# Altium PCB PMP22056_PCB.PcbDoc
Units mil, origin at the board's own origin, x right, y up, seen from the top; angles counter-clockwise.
Board outline 984.25 x 984.25 mil, 2 copper layers (Top Layer, Bottom Layer), stack 62 mil thick; 21 components, 12 nets, 49 pads, 5 vias.
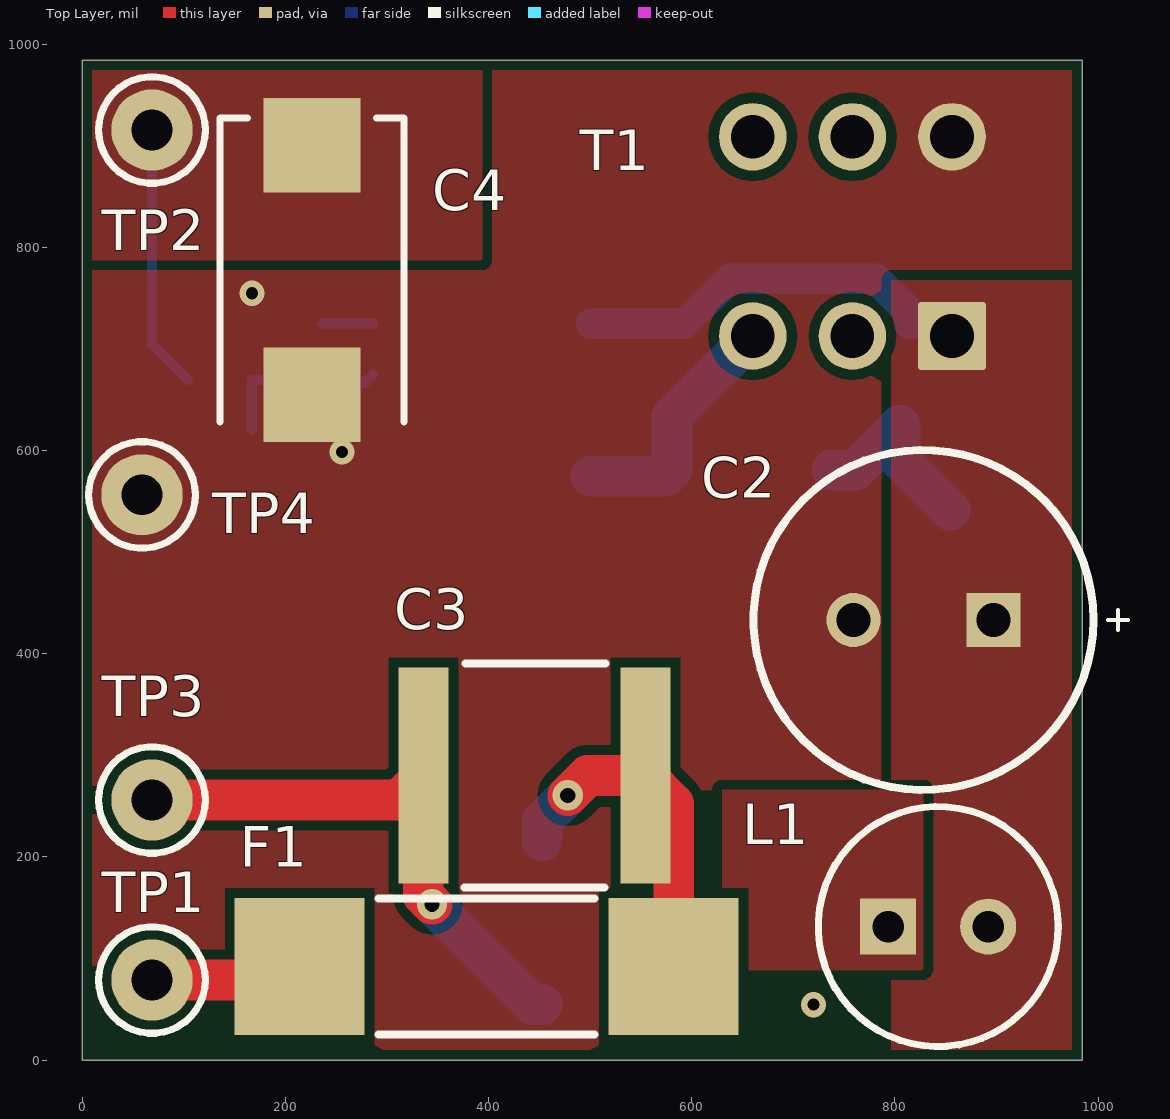
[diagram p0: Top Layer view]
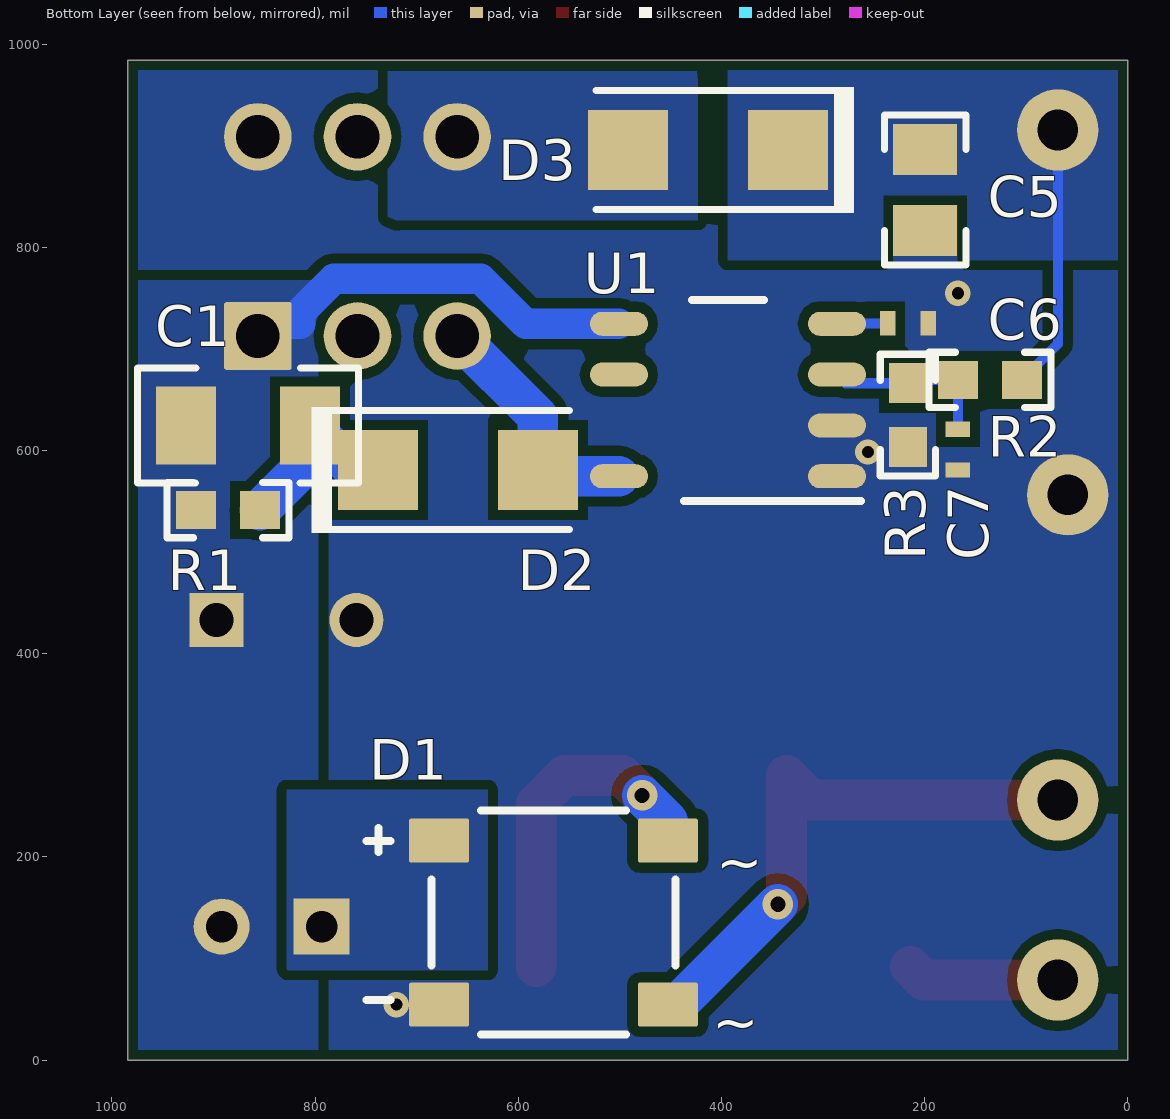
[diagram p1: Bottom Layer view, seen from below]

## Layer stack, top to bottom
Top Solder: solder mask 0.4, Solder Resist, Dk 3.5
Top Layer: signal copper 1.4
Dielectric1: core 59.2, FR-4, Dk 4.8
Bottom Layer: signal copper 1.4
Bottom Solder: solder mask 0.4, Solder Resist, Dk 3.5

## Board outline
0,0 0,984.25 984.25,984.25 984.25,0

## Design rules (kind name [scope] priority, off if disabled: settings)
AcuteAngle [All] p1: minimum=4.50000000000000E+0001 checktracksonly=FALSE
AssemblyTestPointUsage [All] p1: valid=2
BoardOutlineClearance BoardOutlineClearance_MountingHoles [OnCopper and InComponentClass('Mounting Holes')] p1: gap=10 ignorepadtopadclearanceinfootprint=FALSE
BoardOutlineClearance BoardOutlineClearance_Poly [OnCopper and IsPoly] p2: gap=10 ignorepadtopadclearanceinfootprint=FALSE
BoardOutlineClearance [OnCopper and Not InComponentClass('Logo') and not InComponentClass('FiducialMark') and not InRegion(1000,500,4000,800) and not InPoly] p3: gap=10 ignorepadtopadclearanceinfootprint=FALSE
Clearance Clearance_Keepouts [((IsTrack Or IsArc) And Not InPoly) And IsFree and IsKeepOut vs ((IsTrack Or IsArc) And Not InPoly) And IsFree and IsKeepOut] p1: gap=0 ignorepadtopadclearanceinfootprint=FALSE
Clearance Clearance_Poly [InPolygon] p2: gap=10 ignorepadtopadclearanceinfootprint=TRUE
Clearance Clearance_FiducialMark [IsKeepOut and InComponentClass('FiducialMark') vs IsPad and InComponentClass('FiducialMark')] p3: gap=0 ignorepadtopadclearanceinfootprint=FALSE
Clearance [All] p4: gap=7.87 ignorepadtopadclearanceinfootprint=TRUE
ComponentClearance ComponentClearance_MountingHoles_FiducialMarks [InComponentClass('Mounting Holes') vs InComponentClass('FiducialMark')] p1: gap=10 collisioncheckmode=3 verticalgap=10 showdistances=FALSE
ComponentClearance ComponentClearance_Shunt [InComponentClass('Header') vs InComponentClass('Shunt')] p2: gap=0 collisioncheckmode=3 verticalgap=0 showdistances=FALSE
ComponentClearance ComponentClearance_Logo [InComponentClass('Logo')] p3: gap=10 collisioncheckmode=3 verticalgap=10 showdistances=FALSE
ComponentClearance ComponentClearance_ScrewToNut [(HasFootprint('NY PMS 440 0025 PH')) vs (HasFootprint('Keystone_1902C'))] p4: gap=5 collisioncheckmode=3 verticalgap=10 showdistances=FALSE
ComponentClearance ComponentClearance_MountingHoles [InComponentClass('Mounting Holes')] p5: gap=250 collisioncheckmode=3 verticalgap=100000 showdistances=FALSE
ComponentClearance ComponentClearance_SmallPassives [HasFootprint('0201*') or HasFootprint('0402*') or HasFootprint('0508') or HasFootprint('0603*') or HasFootprint('0612') or HasFootprint('0805*') or HasFootprint('0815*') or HasFootprint('0830*') or HasFootprint('1206*') or HasFootprint('1210*') or HasFootprint('1808*') or HasFootprint('1812*') or HasFootprint('1825*') or HasFootprint('2010*') or HasFootprint('2220*') or HasFootprint('2225*') or HasFootprint('2512*') or HasFootprint('2728*') or HasFootprint('3518*') vs HasFootprint('0201*') or HasFootprint('0402*') or HasFootprint('0508') or HasFootprint('0603*') or HasFootprint('0612') or HasFootprint('0805*') or HasFootprint('0815*') or HasFootprint('0830*') or HasFootprint('1206*') or HasFootprint('1210*') or HasFootprint('1808*') or HasFootprint('1812*') or HasFootprint('1825*') or HasFootprint('2010*') or HasFootprint('2220*') or HasFootprint('2225*') or HasFootprint('2512*') or HasFootprint('2728*') or HasFootprint('3518*')] p6: gap=10 collisioncheckmode=3 verticalgap=10 showdistances=FALSE
ComponentClearance ComponentClearance_THtoSMT [IsThruComponent vs IsSMTComponent] p7: gap=10 collisioncheckmode=3 verticalgap=10 showdistances=FALSE
ComponentClearance ComponentClearance_THtoTH [IsThruComponent vs IsThruComponent] p8: gap=10 collisioncheckmode=3 verticalgap=10 showdistances=FALSE
ComponentClearance [All] p9: gap=10 collisioncheckmode=3 verticalgap=10 showdistances=FALSE
DiffPairsRouting [All] p1: maxlimit=100 minlimit=10 mostfreqgap=10 toplayer_minwidth=15 toplayer_maxwidth=15 toplayer_prefwidth=15 bottomlayer_minwidth=15 bottomlayer_maxwidth=15 bottomlayer_prefwidth=15 maxuncoupledlength=1000
FabricationTestPointUsage TestPointUsage [All] p1: valid=2 allowmultiple=FALSE
FabricationTestpoint Testpoint [All] p1: side=3 testpointundercomponent=TRUE minsize=40 maxsize=100 preferedsize=60 minholesize=0 maxholesize=40 preferedholesize=32 testpointgrid=1 allowsidetop=TRUE allowsidebottom=TRUE usegrid=TRUE gridtolerance=0.01
FanoutControl Fanout_LCC [IsLCC] p1: bgadir=Out bgaviamode=Centered fanoutstyle=Auto fanoutdirection=Alternating viagrid=1 // Fanout_LCC (Default Rule)
FanoutControl Fanout_BGA [IsBGA] p2: bgadir=Out bgaviamode=Centered fanoutstyle=Auto fanoutdirection=Alternating viagrid=1 // Fanout_BGA (Default Rule)
FanoutControl Fanout_Default [All] p4: bgadir=Out bgaviamode=Centered fanoutstyle=Auto fanoutdirection=Alternating viagrid=1 // Fanout_Default (Default Rule)
FanoutControl Fanout_Small [(CompPinCount < 5)] p5: bgadir=Out bgaviamode=Centered fanoutstyle=Auto fanoutdirection=OutThenIn viagrid=1 // Fanout_Small (Default Rule)
Height [All] p1: minheight=0 maxheight=393 prefheight=100
HoleSize [All] p1: absolutevalues=TRUE maxlimit=251 minlimit=7.87 maxpercent=80.000 minpercent=20.000
MinimumAnnularRing MinimumAnnularRing_ThermalPadVias [IsVia and InAnyComponent] p1: minimumring=5.91
MinimumAnnularRing [All] p2: minimumring=7.87
MinimumSolderMaskSliver MinimumSolderMaskSliver_Logo [InComponentClass('Logo') vs InComponentClass('Logo')] p1: minsoldermaskwidth=0.7
MinimumSolderMaskSliver [All] p2: minsoldermaskwidth=3.94
PlaneClearance [All] p1: clearance=10
PlaneConnect [All] p1: planeconnectstyle=Direct reliefexpansion=10 reliefentries=4 reliefconductorwidth=10 reliefairgap=10
PolygonConnect [All] p1: connectstyle=Direct reliefconductorwidth=10 reliefentries=4 polygonreliefangle="90 Angle" airgapwidth=10
RoutingVias ThermalPadVias [IsVia and InAnyComponent] p1: holewidth=7.87 width=19.68 viastyle="Through Hole" minholewidth=7.87 minwidth=19.68 maxholewidth=12.99 maxwidth=23.62
RoutingVias [All] p2: holewidth=16 width=34 viastyle="Through Hole" minholewidth=7.87 minwidth=26 maxholewidth=40 maxwidth=65
SilkToBoardRegionClearance [Not ((IsComment or IsDesignator) And (Hide <> 'False')) and not InRegion(1000,500,4000,800)] p1:
SilkToSilkClearance SilkToSilkClearance_Pb-FreeLogo [(HasFootprint('Pb-Free_Overlay_Medium') OR HasFootprint('Pb-Free_Overlay_Small')) vs (HasFootprint('Pb-Free_Overlay_Medium') OR HasFootprint('Pb-Free_Overlay_Small'))] p1: silktosilkclearance=0
SilkToSilkClearance [All] p2: silktosilkclearance=3.94
SilkToSolderMaskClearance SilkToComponentPadClearance [(IsPad or IsFill or IsRegion) and InAnycomponent] p1: minsilkscreentomaskgap=5 clearancetoexposedcopper=TRUE
SilkToSolderMaskClearance "Silk to Solder Mask Opening" [All] p2: minsilkscreentomaskgap=3.94 clearancetoexposedcopper=FALSE
SolderMaskExpansion [All] p1: expansion=1.97
UnRoutedNet [All] p1: checkbadconnections=TRUE
Width [All] p1: maxlimit=100 minlimit=6 preferedwidth=10 checkconnectedcopper=TRUE
12 further rules are at their usual default settings.

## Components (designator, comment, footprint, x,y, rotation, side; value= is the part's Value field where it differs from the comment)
C1 "C3216C0G2J471J085AA" 1206M 866.14,624.61 r180 bottom value=470pF
C2 "400AX4.7MTA8X9" AX_800x900 828.22,433.07 r180 top value=4.7uF
C3 "LDEPD2100KA5N00" 2220_330_N 445.28,280.08 r180 top value=0.01uF
C4 "6TPE470MAZU" 7343-20 226.38,777.56 r270 top value=470uF
C5 "C2012X7R0J106M125AB" 0805_HV 199.46,856.3 r270 bottom value=10uF
C6 "CGA2B3X7R1H104K050BB" 0402S 216.46,724.99 r180 bottom value=0.1uF
C7 "CGA2B2X8R1H221K050BA" 0402S 167.32,600.71 r90 bottom value=220pF
D1 "CD-MBL206SL" CD-MBL2xxS 565.35,135.29 r180 bottom value=600V
D2 "STTH1R06A" SMA 659.45,580.71 r180 bottom value=600V
D3 "MBRA340T3G" SMA 413.39,895.67 r0 bottom value=40V
F1 "0443.500DR" FUSE_0443 398.28,91.98 r180 top
L1 "7447462102" WE-TI_5075 842.73,131.35 r0 top value=1mH
R1 "CRCW0603100KJNEA" 0603 885.83,541.34 r0 bottom value=100k
R2 "CRCW060388K7FKEA" 0603 135.83,669.29 r180 bottom value=88.7k
R3 "CRCW060322K1FKEA" 0603 216.54,634.65 r270 bottom value=22.1k
T1 "750318452" "FP-750318452_XFMR_10MM16_8MM26_PTH_6-Recommended_Land Pattern" 758.27,810.64 r90 top
TP1 "5002" Keystone5002 68.9,78.74 r90 top value=White
TP2 "5000" Keystone5000 68.9,915.35 r90 top value=Red
TP3 "5002" Keystone5002 68.9,255.91 r90 top value=White
TP4 "5001" Keystone5001 59.06,556.21 r90 top value=Black
U1 "UCC28880DR" D0007A_N 393.7,649.61 r0 bottom

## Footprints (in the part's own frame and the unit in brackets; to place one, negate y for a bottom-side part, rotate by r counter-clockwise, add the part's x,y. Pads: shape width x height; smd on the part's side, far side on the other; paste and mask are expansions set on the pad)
0402S [mil] "Based on C0402S footprint from PADS legacy"
  rect 15x24 smd: 1(-20,0) 2(20,0)
  body extent -22,-12 22,12, height 24
0603 [mm] "0603 from SM-752 data"
  rect 1x0.95 smd: 1(-0.8,0) 2(0.8,0)
  silkscreen extent -1.52,-0.69 1.52,0.69, body extent -0.87,-0.47 0.87,0.47, height 1
0805_HV [mil] "0805 with 30mil clearance between pads"
  rect 50x63 smd: 1(-40,0) 2(40,0)
  silkscreen extent -74,-40 74,40, body extent -43,-29 43,29, height 57
1206M [mm] "1206 from SM-752 data"
  rect 1.5x1.95 smd: 1(-1.55,0) 2(1.55,0)
  silkscreen extent -2.76,-1.44 2.76,1.44, body extent -1.7,-0.9 1.7,0.9, height 1.35
2220_330_N [mm] "Chip Capacitor, 2-Leads, Body 5.70x5.00mm, IPC Medium Density"
  rect 1.25x5.4 smd: 1(-2.775,0) 2(2.775,0)
  silkscreen extent -1.78,-2.8 1.75,2.8, body extent -3.05,-2.7 3.05,2.7, height 3.3
7343-20 [mm] "Medium density IPC, based on Kemet case V from T495 datasheet"
  rect 2.37x2.43 smd: 1(-3.12,0) 2(3.12,0)
  silkscreen extent -3.8,-2.3 3.8,2.3, body extent -3.8,-2.3 3.8,2.3, height 2
AX_800x900 [mm] "TH, 2-Leads, Dia 8mm, Pin Spacing 3.5mm"
  rect 1.35x1.35 hole 0.85: 1(-1.75,0)
  round 1.35 hole 0.85: 2(1.75,0)
  silkscreen extent -5.11,-4.25 4.25,4.25, body extent -4.25,-4.25 4.26,4.25, height 10.51
CD-MBL2xxS [mm] "SMD, 4-Leads, Body 5.72x4.1mm"
  rrect9% 1.5x1.1 smd: 1(-2.86,2.05) 2(2.86,2.05) 3(2.86,-2.05) 4(-2.86,-2.05)
  silkscreen extent -4.67,-2.8 3.05,2.8, body extent -2.9,-2.65 2.9,2.65, height 1.02
D0007A_N [mm] "SOIC, 7-Leads, Body 4.9x3.9mm, Pitch 1.27mm, IPC Medium Density"
  oval 1.45x0.6 smd: 1(-2.725,1.905) 2(-2.725,0.635) 3(-2.725,-0.635) 4(-2.725,-1.905) 5(2.725,-1.905) 6(2.725,-0.635) 8(2.725,1.905)
  silkscreen extent -3.32,-2.5 1.1,2.52, body extent -3.01,-2.45 3.01,2.45, height 1.75
"FP-750318452_XFMR_10MM16_8MM26_PTH_6-Recommended_Land Pattern" [mm]
  rrect6% 1.69x1.69 hole 1.09 paste-1000 mask+0: 1(-2.49,-2.49)
  round 1.69 hole 1.09 paste-1000 mask+0: 2(-2.49,0) 3(-2.49,2.49) 4(2.49,2.49) 5(2.49,0) 6(2.49,-2.49)
  body extent -4.23,-5.18 4.23,5.18, height 0.25
FUSE_0443 [mm] "LITTELFUSE"
  rect 3.25x3.43 smd: 1(-4.675,0) 2(4.675,0)
  silkscreen extent -2.7,-1.7 2.7,1.7, body extent -5.05,-1.56 5.05,1.56, height 3.12
Keystone5000 [mil] "For Keystone 500x miniature loop terminals"
  round 80 hole 40: 1(0,0)
  silkscreen extent -52,-52 52,52, body extent -49,-49 49,49, height 182
Keystone5001 [mil] "For Keystone 500x miniature loop terminals"
  round 80 hole 40: 1(0,0)
  silkscreen extent -52,-52 52,52, body extent -49,-49 49,49, height 182
Keystone5002 [mil] "For Keystone 500x miniature loop terminals"
  round 80 hole 40: 1(0,0)
  silkscreen extent -52,-52 52,52, body extent -49,-49 49,49, height 182
SMA [mm] "Molded Diode, 2-Leads, Body 4.3x2.6mm, IPC Medium Density, based on OnSemi component dimensions and land pattern"
  rect 2x2 smd: 1(-2,0) 2(2,0)
  silkscreen extent -3.66,-1.57 2.79,1.57, body extent -2.6,-1.3 2.6,1.3, height 2.42
WE-TI_5075 [mm] "Wurth WE-TI 5075"
  rect 1.4x1.4 hole 0.787: 1(-1.25,0)
  round 1.4 hole 0.787: 2(1.25,0)
  silkscreen extent -3,-3 3,3, body extent -3,-3 3,3, height 8.5

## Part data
C1: library part CMP-0008645-1, "CAP, CERM, 470 pF, 630 V, +/- 5%, C0G/NP0, 1206", Cap_Case=1206, Manufacturer=TDK, Supplier Part Number 1=445-2340-1-ND, TempCo=C0G/NP0, Tolerance_%=5%, Value1=Unknown, Value2=630V, ValueDisplayed=470pF
C2: library part CMP-0009969-2, "CAP, AL, 4.7 uF, 400 V, +/- 20%, TH", Cap_Case=8x9mm, Manufacturer=Rubycon, Supplier Part Number 1=400AX4.7MTA8X9-ND, Tolerance_%=20%, Value1=Unknown, Value2=400V, ValueDisplayed=4.7uF
C3: library part CMP-0012521-1, "CAP, Film, 0.01 uF, 630 V, +/- 10%, AEC-Q200 Grade 1, 2220 SMD", Cap_Case=2220, Manufacturer=Kemet, Supplier Part Number 1=399-5482-1-ND, Tolerance_%=10%, Value1=Unknown, Value2=630V, ValueDisplayed=0.01uF
C4: library part CMP-0012638-4, "CAP, Tantalum Polymer, 470 uF, 6.3 V, +/- 20%, 0.035 ohm, 7343-20 SMD", Cap_Case=7343-20, Manufacturer=Panasonic, Tolerance_%=20%, Value1="0.035 ohm", Value2=6.3V, ValueDisplayed=470uF
C5: "CAP, CERM, 10 µF, 6.3 V, +/- 20%, X7R, 0805", Cap_Case=0805, Manufacturer=TDK, Supplier Part Number 1=445-7594-1-ND, TempCo=X7R, Tolerance_%=20, Value1=Unknown, Value2=6.3V, ValueDisplayed=10µF
C6: library part CMP-0006325-1, "CAP, CERM, 0.1 uF, 50 V, +/- 10%, X7R, AEC-Q200 Grade 1, 0402", Cap_Case=0402, Manufacturer=TDK, Supplier Part Number 1=445-6899-1-ND, TempCo=X7R, Tolerance_%=10%, Value1="0.039064 ohm", Value2=50V, ValueDisplayed=0.1uF
C7: library part CMP-0084239-1, "CAP, CERM, 220 pF, 50 V,+/- 10%, X8R, AEC-Q200 Grade 0, 0402", Cap_Case=0402, Manufacturer=TDK, TempCo=X8R, Tolerance_%=10%, Value2=50V, ValueDisplayed=220pF
D1: library part CMP-0067544-2, "Diode, P-N-Bridge, 600 V, 2 A, 5.8x5.3mm", Manufacturer=Bourns, Value1=2A, Value2=0.96V
D2: "Diode, Ultrafast, 600 V, 1 A, SMA", Manufacturer="ST Microelectronics", Supplier Part Number 1=497-3765-1-ND, Value1=1A, Value2=1V
D3: "Diode, Schottky, 40 V, 3 A, SMA", Manufacturer="ON Semiconductor", Supplier Part Number 1=1431078, Value1=3A, Value2=0.415V
F1: library part CMP-0003466-1, "Fuse, 0.5 A, 250VAC/VDC, SMD", Irating_A=500mA, Manufacturer=Littelfuse, Supplier Part Number 1=F2904CT-ND
L1: "Inductor, Unshielded Drum Core, Ferrite, 1 mH, 0.25 A, 4.38 ohm, TH", Manufacturer="Wurth Elektronik eiSos", Supplier Part Number 1=732-2576-ND, Value1=1mH, Value2=0.25A
R1: library part CMP-0025698-1, "RES, 100 k, 5%, 0.1 W, 0603", Manufacturer=Vishay-Dale, Power_W=100mW, Supplier Part Number 1=541-100KGCT-ND, TempCo="200 ppm/C", Tolerance_%=5%, Value2=0.1W, Value_Code=100k
R2: "RES, 88.7 k, 1%, 0.1 W, 0603", Manufacturer=Vishay-Dale, Power_W=0.1, Supplier Part Number 1=541-88.7KHCT-ND, TempCo="100 ppm/C", Tolerance_%=1, Value1=1%, Value2=0.1W, Value_Code=88k7, ValueDisplayed=88.7k
R3: "RES, 22.1 k, 1%, 0.1 W, 0603", Manufacturer=Vishay-Dale, Power_W=0.1, Supplier Part Number 1=541-22.1KHCT-ND, TempCo="100 ppm/C", Tolerance_%=1, Value1=1%, Value2=0.1W, Value_Code=22k1, ValueDisplayed=22.1k
T1: library part CMP-0087346-1, "TRANSFORMER 10mH, Leak 150uH, 20:1, 50kHz, 1500VAC", Manufacturer="Wurth Electronics"
TP1 TP3: "Test Point, Miniature, White, TH", Manufacturer=Keystone, Supplier Part Number 1=5002K-ND
TP2: "Test Point, Miniature, Red, TH", Manufacturer=Keystone, Supplier Part Number 1=5000K-ND
TP4: "Test Point, Miniature, Black, TH", Manufacturer=Keystone, Supplier Part Number 1=5001K-ND
U1: "700-V Lowest Quiescent Current Off-Line Switcher, D0007A", Alternate Manufacturer=None, Manufacturer="Texas Instruments"

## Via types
v1: diameter 25, hole 12, Top Layer to Bottom Layer, 3 vias
v2: diameter 30, hole 15, Top Layer to Bottom Layer, 2 vias

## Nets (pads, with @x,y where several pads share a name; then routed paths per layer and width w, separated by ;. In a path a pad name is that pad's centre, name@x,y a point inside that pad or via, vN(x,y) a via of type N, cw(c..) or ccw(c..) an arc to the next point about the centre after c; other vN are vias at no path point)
GND: C2.2 C4.2 C5.2 C6.2 C7.1 D1.4 R3.2 T1.6 TP4.1 U1.1 U1.2
  other v1: 719.99,54.58 255.91,598.43 167.32,754.76
NetC1_1: C1.1 C2.1 L1.2 R1.2 T1.1 U1.5 | length 403.4
  Bottom Layer w30: U1.5 592.84,724.61 636.98,768.75 781.52,768.75 814.41,735.86 814.41,724.61 844.3,724.61 T1.1
NetC1_2: C1.2 D2.1 R1.1 | length 188.8
  Bottom Layer w40: D2.1 761.22,580.71 C1.2 805.12,590.55 R1.1
NetC3_1: C3.1 D1.2 F1.1 | length 339.1
  Top Layer w40: v2(478.15,260.4) 497.84,280.08 C3.1 582.34,252.28 F1.1
  Bottom Layer w40: D1.2 452.76,235 v2(478.15,260.4)
NetC3_2: C3.2 D1.3 TP3.1 | length 556.5
  Top Layer w40: TP3.1 311.85,255.91 C3.2 336.02,161.86 v2(344.49,153.4)
  Bottom Layer w40: v2(344.49,153.4) 443.31,54.58 D1.3
NetC4_1: C4.1 C5.1 D3.1 R2.2 TP2.1 | length 260.7
  Bottom Layer w10: TP2.1 68.9,704.72 R2.2
NetC6_1: C6.1 U1.4 | length 50.1
  Bottom Layer w10: C6.1 286.03,724.99 U1.4
NetC7_2: C7.2 R2.1 R3.1 U1.3 | length 172.5
  Bottom Layer w10: C7.2 R2.1 213.39,669.29 R3.1 277.95,666.14 U1.3
NetD1_1: D1.1 L1.1
NetD2_2: D2.2 T1.3 U1.8 | length 247.1
  Bottom Layer w40: U1.8 574.61,574.61 D2.2 580.71,633.08 T1.3
NetD3_2: D3.2 T1.4
NetF1_2: F1.2 TP1.1 | length 150.8
  Top Layer w40: TP1.1 200.98,78.74 F1.2
pads on no net: T1.2 T1.5 U1.6

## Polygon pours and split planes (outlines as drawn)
GND on Top Layer "TOP_LAYER_GND_P014" (solid, remove dead copper, pour order 14): 0,984.25 984.25,984.25 984.25,0 -9.84,0 -9.84,974.41
NetC4_1 on Top Layer "TOP_LAYER_NETC4_1_P012" (solid, remove dead copper, pour order 12): 393.7,787.4 0,787.4 0,984.25 393.7,984.25
NetC1_1 on Top Layer "TOP_LAYER_NETC1_1_P004" (solid, remove dead copper, pour order 4): 984.25,767.72 984.25,0 796.68,0 796.68,767.16 797.24,767.72
NetD1_1 on Top Layer "TOP_LAYER_NETD1_1_P000" (solid, remove dead copper, pour order 0): 629.92,265.75 629.94,265.76 828.02,265.76 828.02,89.83 826.77,88.58 629.92,88.58
GND on Bottom Layer "BOTTOM_LAYER_GND_P016" (solid, remove dead copper, pour order 16): 0,984.25 984.25,984.25 984.25,0 -9.84,0 -9.84,974.41
NetC4_1 on Bottom Layer "BOTTOM_LAYER_NETC4_1_P010" (solid, remove dead copper, pour order 10): 393.7,787.4 0,787.4 0,984.25 393.7,984.25
NetD3_2 on Bottom Layer "BOTTOM_LAYER_NETD3_2_P008" (solid, remove dead copper, pour order 8): 423.23,974.41 424.4,973.24 728.35,973.24 728.35,816.93 718.5,826.77 423.23,826.77
NetC1_1 on Bottom Layer "BOTTOM_LAYER_NETC1_1_P006" (solid, remove dead copper, pour order 6): 984.25,767.72 984.25,0 796.68,0 796.68,767.16 797.24,767.72
NetD1_1 on Bottom Layer "BOTTOM_LAYER_NETD1_1_P002" (solid, remove dead copper, pour order 2): 629.92,265.75 629.94,265.76 828.02,265.76 828.02,89.83 826.77,88.58 629.92,88.58

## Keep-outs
Keep-Out Layer:
  text ".Layer_Name" at 577,-858.49 h60

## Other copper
Top Layer:
  text ".Layer_Name" at 577,-858.49 h60
Bottom Layer:
  text ".Layer_Name" at 577,-858.49 h60

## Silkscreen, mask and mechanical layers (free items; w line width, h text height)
Top Overlay:
  text "'.PRJ_Number'.PCB_Rev" at 1845,125.77 h108.27
  text ".Layer_Name" at 577,-858.49 h60
Bottom Overlay:
  text ".Layer_Name" at 577,-858.49 h60
Top Paste:
  text ".Layer_Name" at 577,-858.49 h60
Bottom Paste:
  text ".Layer_Name" at 577,-858.49 h60
Top Solder:
  text ".Layer_Name" at 577,-858.49 h60
  text ".Layer_Name" at 577,-858.49 h60
Bottom Solder:
  text ".Layer_Name" at 577,-858.49 h60
Drill Guide:
  text ".Layer_Name" at 577,-858.49 h60
M1 Board Outline:
  text ".Layer_Name" at 577,-858.49 h60
M2 Board Dimensions:
  rectangle: 0,-275 125,-150
  rectangle: 125,-400 500,-275
  lines w7: 0,-275 1000,-275 ; 125,-400 125,-150 ; 250,-400 250,-150 ; 500,-400 500,-150 ; 750,-400 750,-150 ; 0,-400 1000,-400 1000,-150 0,-150 0,-400
  text ".Layer_Name" at 577,-858.49 h60
M3 3D STEP Top:
  text ".Layer_Name" at 577,-858.49 h60
M4 3D STEP Bottom:
  text ".Layer_Name" at 577,-858.49 h60
M5 Assembly Top:
  lines w10: -292,-930.17 6308,-930.17 ; -292,-726.83 6310,-726.83 ; -292,-523.5 -292,-1133.5 3713,-1133.5 6310,-1133.5 6310,-523.5 -291.5,-523.5 -291.5,-1133.5 1284,-1133.5 ; 2173,-1133.5 2173,-523.5 ; 3440,-726.83 3440,-523.5 ; 4280,-726.83 4280,-523.5 ; 4902,-1140 4902,-937.17
  text "COMPONENTS MARKED 'DNP' SHOULD NOT BE POPULATED." at 1153.5,-318.5 h60
  text "ASSEMBLY VARIANT:" at 1153,-434 h60
  text ".VariantName" at 2189,-434 h60
  text "PCB VIEWED FROM TOP SIDE" at -228.5,-655.67 h60
  text "BOARD #:" at 2248,-655.67 h60
  text ".PRJ_Number" at 2793.5,-655.67 h60
  text "REV:" at 3638,-655.67 h60
  text ".PCB_Rev" at 3929.5,-655.67 h60
  text "SVN REV:" at 4476,-655.67 h60
  text ".VersionControl_RevNumber" at 4982,-655.67 h60
  text "TID #:" at 2248,-859 h60
  text ".TID" at 2793.5,-859 h60
  text "PLOT NAME =" at -228.5,-1064.34 h60
  text ".plot_File_Name" at 577,-1064.34 h60
  text "GENERATED    :" at 2250,-1064.34 h60
  text ".Print_Date" at 3119.5,-1064.34 h60
  text ".Print_Time" at 3848.5,-1064.34 h60
  text "TEXAS INSTRUMENTS" at 5113,-1064.34 h60
M6 Assembly Bottom:
  lines w10: -292.5,-727.33 6309.5,-727.33 ; -290.5,-930.67 6309.5,-930.67 ; 1115.5,-1140.5 1115.5,-937.67 ; 1737.5,-727.33 1737.5,-524 ; 2577.5,-727.33 2577.5,-524 ; 3844.5,-1134 3844.5,-524 ; 4733.5,-1134 6309,-1134 6309,-524 -292.5,-524 -292.5,-1134 2304.5,-1134 6309.5,-1134 6309.5,-524
  text "COMPONENTS MARKED 'DNP' SHOULD NOT BE POPULATED." at 6102,-318 h60
  text ".VariantName" at 5058,-434 h60
  text "ASSEMBLY VARIANT:" at 6097,-434 h60
  text ".VersionControl_RevNumber" at 1035.5,-656.17 h60
  text "SVN REV:" at 1541.5,-656.17 h60
  text ".PCB_Rev" at 2088,-656.17 h60
  text "REV:" at 2379.5,-656.17 h60
  text ".PRJ_Number" at 3224,-656.17 h60
  text "BOARD #:" at 3769.5,-656.17 h60
  text "PCB VIEWED FROM BOTTOM SIDE" at 6246,-656.17 h60
  text ".TID" at 3224,-859.5 h60
  text "TID #:" at 3769.5,-859.5 h60
  text "TEXAS INSTRUMENTS" at 904.5,-1064.84 h60
  text ".Print_Time" at 2169,-1064.84 h60
  text ".Print_Date" at 2898,-1064.84 h60
  text "GENERATED    :" at 3767.5,-1064.84 h60
  text ".plot_File_Name" at 5440.5,-1064.84 h60
  text "PLOT NAME =" at 6246,-1064.84 h60
M9 Title Sheet:
  drawing of 57 lines, arcs and shapes, not listed
  text "1" at 739.84,8036.5 h70
  text "2" at 3235.5,8036.5 h70
  text "3" at 5724.84,8036.5 h70
  text "4" at 8231.51,8036.5 h70
  text "5" at 10730.5,8036.5 h70
  text "6" at 13235.5,8036.5 h70
  text "A" at -416.5,6893.5 h70
  text "A" at 14383.5,6893.5 h70
  text "B" at -416.5,4513.5 h70
  text "B" at 14383.5,4513.5 h70
  text "C" at -416.5,2138.5 h70
  text "C" at 14383.5,2138.5 h70
  text "PROJECT TITLE:" at 11343.5,277.5 h45
  text ".PRJ_Title" at 11393.5,144.17 h70
  text "DESIGNED FOR:" at 11343.5,-23.5 h45
  text ".PRJ_Customer" at 11393.5,-163.5 h70
  text "D" at -416.5,-231.5 h70
  text "D" at 14383.5,-231.5 h70
  text "FILE NAME:" at 11343.5,-323.5 h45
  text ".PCB_File_Name_No_Path" at 11393.5,-443.5 h70
  text "Texas Instruments (TI) and/or its licensors do not warrant the accuracy or completeness of this specification" at 6374,-605.34 h45
  text "ENGINEER:" at 11343.5,-613.5 h45
  text "LAYOUT BY:" at 12848.5,-613.5 h45
  text "or any information contained therein. TI and/or its licensors do not warrant that this design will meet" at 6329.01,-718 h45
  text ".PRJ_Engineer" at 11393.5,-768.49 h70
  text ".PCB_Layout" at 12899,-768.49 h70
  text "the specifications, will be suitable for your application or fit for any particular purpose, or will operate in" at 6329.01,-830.67 h45
  text ".Layer_Name" at 577,-858.49 h60
  text "ALTIUM DESIGNER VERSION:" at 12848.5,-923.5 h45
  text "an implementation. TI and/or its licensors do not warrant that the design is production worthy. You should" at 6329.01,-943.33 h45
  text "completely validate and test your design implementation to confirm the system functionality for your application." at 6374,-1056 h45
  text ".print_Scale" at 11393.5,-1056.83 h70
  text ".Application_BuildNumber" at 12899,-1056.83 h70
  text "1" at 739.84,-1263.5 h70
  text "2" at 3235.5,-1263.5 h70
  text "3" at 5724.84,-1263.5 h70
  text "4" at 8231.51,-1263.5 h70
  text "5" at 10730.5,-1263.5 h70
  text "6" at 13235.5,-1263.5 h70
M10 Fab Notes:
  drawing of 189 lines, arcs and shapes, not listed
  text "DESIGN INFORMATION" at 12382.02,6356.17 h60
  text "MIN. TRACK WIDTH:" at 11737.46,6224.05 h60
  text "8" at 12833.7,6224.05 h60
  text "MIL" at 12988.46,6224.05 h60
  text "MIN. CLEARANCE:" at 11737.46,6099.92 h60
  text "0.2" at 12773.7,6099.93 h60
  text "mm" at 12988.46,6099.92 h60
  text "MIN. VIA PAD SIZE:" at 11737.46,5975.8 h60
  text "24" at 12803.71,5975.8 h60
  text "MIL" at 12988.46,5975.8 h60
  text "0.05mm (2MIL)" at 12432.46,5845.9 h60
  text "MINIMUM ANNULAR RING" at 11408.23,5837.67 h60
  text "EXTERNAL" at 13140.46,5837.67 h60
  text "PER" at 11608.23,5727.55 h60
  text "IPC-D-275 CLASS 2 LEVEL C" at 11828.23,5727.54 h60
  text "MIL, HOLES" at 13316.46,5627.07 h60
  text "+/-" at 12924,5618.48 h60
  text "+/-" at 13778,5618.48 h60
  text "REGISTRATION TOLERANCES:" at 11408.23,5617.42 h60
  text "METAL" at 12608,5617.42 h60
  text "5" at 13184.2,5617.42 h60
  text "3" at 14017.2,5617.42 h60
  text "MIL" at 14133.46,5617.42 h60
  text "HOLE SIZE TOLERANCE (UNLESS OTHERWISE SPECIFIED):" at 11408.23,5519.1 h60
  text "+/-" at 13778,5516.23 h60
  text "3" at 14017.2,5515.17 h60
  text "MIL" at 14133.46,5515.17 h60
  text "MATERIAL:" at 11333.46,5377.52 h60
  text "FR-4 High Tg" at 12319.9,5249 h60
  text "X" at 12175.46,5241.01 h60
  text "FR-408" at 11754.46,5236.49 h60
  text "OTHER" at 13242.46,5236.49 h60
  text "62 MIL (1.6mm) +/-10%" at 12074.56,5093.46 h60
  text "X" at 11954.46,5091.01 h60
  text "THICKNESS:" at 11408.23,5085.24 h60
  text "OTHER" at 13359.46,5085.24 h60
  text "TOLERANCE:" at 11408.23,4946.92 h60
  text "X" at 12256.46,4946.92 h60
  text "ANSI IPC-6012 TYPE 3 CLASS 2" at 12434.48,4946.92 h60
  text "OTHER +/-" at 12434.46,4802.73 h60
  text "BOW & TWIST:" at 11408.23,4657.54 h60
  text "X" at 12256.46,4657.54 h60
  text "ANSI IPC-6012 TYPE 3 CLASS 2" at 12434.48,4657.54 h60
  text "OTHER +/-" at 12434.46,4510.85 h60
  text "DRILLING:" at 11333.46,4380.23 h60
  text "NC_DRILL FILES" at 13094.46,4275.04 h60
  text "REFERENCE:" at 11408.23,4271.1 h60
  text "X" at 12065.46,4271.01 h60
  text "AS SHOWN" at 12243.46,4271.1 h60
  text "X" at 12966.46,4271.1 h60
  text "OTHER" at 13392.46,4128.85 h60
  text "PTH COPPER THICKNESS:" at 11407.91,4125.32 h60
  text "X" at 12547.14,4125.32 h60
  text "20-30 um" at 12675.14,4125.32 h60
  text "BOARD FINISH:" at 11333.46,3977.73 h60
  text "SILKSCREEN:" at 11488.68,3867.6 h60
  text "X" at 12446.46,3867.6 h60
  text "TOP" at 12563.46,3867.6 h60
  text "X" at 12956.46,3867.6 h60
  text "BOTTOM" at 13074.46,3867.6 h60
  text "SILKSCREEN COLOR:" at 11488.68,3712.41 h60
  text "X" at 12445.46,3712.41 h60
  text "WHITE" at 12563.46,3712.41 h60
  text "OTHER" at 13074.46,3712.41 h60
  text "X" at 12576.46,3568.96 h60
  text "GREEN" at 12694.46,3568.96 h60
  text "OTHER" at 13312.46,3568.96 h60
  text "SOLDER RESIST COLOR:" at 11488.68,3562.1 h60
  text "X" at 12576.46,3414.71 h60
  text "MATTE" at 12694.46,3414.71 h60
  text "SEMI-GLOSS" at 13312,3414.07 h60
  text "IMMERSION GOLD (ENIG)" at 12394.46,3241.94 h60
  text "ENEPIG" at 13732,3234.72 h60
  text "SURFACE FINISH:" at 11333.46,3233.72 h60
  text "X" at 12216.46,3233.72 h60
  text "IMM. TIN/SILVER OR EQUIV" at 11663,3096.4 h60
  text "OTHER" at 13094.46,3092.47 h60
  text "ARRAY/PANEL:" at 11333.46,2937.09 h60
  text "CUT AND TRIM PER M1 BOARD OUTLINE" at 12394.46,2928.87 h60
  text "N.C. ROUTE" at 12394.46,2792.9 h60
  text "X" at 13082.46,2792.9 h60
  text "V. SCORE" at 13260.46,2792.9 h60
  text "CERTIFICATION:" at 11333.46,2663.77 h60
  text "MATERIALS AND WORKMANSHIP FOR ALL PCBS" at 12058.46,2663.77 h60
  text "TO MEET OR EXCEED THE REQUIREMENTS OF:" at 12058.46,2569.71 h60
  text "X" at 11695.97,2441.08 h60
  text "ANSI IPC-A-600F CLASS ->" at 11823.96,2441.08 h60
  text "X" at 13471.97,2441.08 h60
  text "2" at 13581.96,2441.08 h60
  text "1" at 13266.96,2439.58 h60
  text "3" at 13935.96,2439.58 h60
  text "X" at 12507.97,2293.39 h60
  text "RoHS" at 12635.96,2293.39 h60
  text "OTHER" at 13280.36,2293.39 h60
  text "PER ORDER" at 13677.42,2293.39 h60
  text "ALL BOARDS MUST MEET OR EXCEED UL94-V0 REQUIREMENTS." at 11361,2139.57 h60
  text "PCB MUST BEAR THE UL94V-0 UL REGISTERED MATERIAL ID NUMBER" at 11361,2023.5 h60
  text "ADDITIONAL REQUIREMENTS:" at 11333.46,1854.08 h60
  text "MICROSECTION:" at 11408.23,1746.95 h60
  text "YES" at 12313.96,1746.95 h60
  text "REQUIRED" at 13175.46,1602.62 h60
  text "BARE BOARD ELEC. TEST:" at 11408.23,1599.76 h60
  text "NONE" at 12713.96,1599.76 h60
  text "X" at 13057.46,1599.76 h60
  text "PER ORDER" at 13767.46,1599.76 h60
  text "XX MIL VIAS REQUIRE NON-CONDUCTIVE FILL AND PLANARIZE" at 11576.38,1394.82 h59
  text "XX MIL VIAS REQUIRE CONDUCTIVE FILL AND PLANARIZE" at 11584.38,1290.84 h60
  text "OUTER XX MIL TRACES REQUIRE 50 OHM SINGLE-ENDED IMPEDANCE" at 11583.39,1127.46 h58
  text "LAYER 2 & 3 (INNER LAYERS) XX MIL WIDE, XX MIL SPACE / TRACES REQUIRE 100 OHM DIFFERENTIAL IMPEDANCE" at 11575.39,891.74 h60
  text ".Layer_Name" at 577,-858.49 h60
M11 Gerber Information:
  lines w10: -292,-930.17 6308,-930.17 ; -292,-726.83 6310,-726.83 ; -292,-523.5 -292,-1133.5 3713,-1133.5 6310,-1133.5 6310,-523.5 -291.5,-523.5 -291.5,-1133.5 1284,-1133.5 ; 2173,-1133.5 2173,-523.5 ; 3440,-726.83 3440,-523.5 ; 4280,-726.83 4280,-523.5 ; 4902,-1140 4902,-937.17
  text "ALL ARTWORK VIEWED FROM TOP SIDE" at -228.5,-655.67 h60
  text "BOARD #:" at 2248,-655.67 h60
  text ".PRJ_Number" at 2793.5,-655.67 h60
  text "REV:" at 3638,-655.67 h60
  text ".PCB_Rev" at 3929.5,-655.67 h60
  text "SVN REV:" at 4476,-655.67 h60
  text ".VersionControl_RevNumber" at 4982,-655.67 h60
  text "LAYER NAME =" at -228.5,-858.49 h60
  text "TID #:" at 2248,-859 h60
  text ".TID" at 2793.5,-859 h60
  text "PLOT NAME =" at -228.5,-1064.34 h60
  text ".plot_File_Name" at 577,-1064.34 h60
  text "GENERATED    :" at 2250,-1064.34 h60
  text ".Print_Date" at 3119.5,-1064.34 h60
  text ".Print_Time" at 3848.5,-1064.34 h60
  text "TEXAS INSTRUMENTS" at 5113,-1064.34 h60
M12 Stackup:
  drawing of 191 lines, arcs and shapes, not listed
  text "Layer" at 9811.59,7762.44 h60
  text "Name" at 10221.51,7762.44 h60
  text "Material" at 11151.25,7762.44 h60
  text "Thickness" at 12011.02,7762.44 h60
  text "Constant" at 12660.85,7762.44 h60
  text "Board Layer Stack" at 13230.71,7762.44 h60
  text "1" at 9811.59,7642.44 h60
  text "Top Overlay" at 10221.51,7642.44 h60
  text "2" at 9811.59,7522.44 h60
  text "Top Solder" at 10221.51,7522.44 h60
  text "Solder Resist" at 11151.25,7522.44 h60
  text "0.40mil" at 12011.02,7522.44 h60
  text "3.5" at 12660.85,7522.44 h60
  text "3" at 9811.59,7402.44 h60
  text "Top Layer" at 10221.51,7402.44 h60
  text "Copper" at 11151.25,7402.44 h60
  text "1.40mil" at 12011.02,7402.44 h60
  text "4" at 9811.59,7282.44 h60
  text "Dielectric1" at 10221.51,7282.44 h60
  text "FR-4" at 11151.25,7282.44 h60
  text "59.20mil" at 12011.02,7282.44 h60
  text "4.8" at 12660.85,7282.44 h60
  text "5" at 9811.59,7162.44 h60
  text "Bottom Layer" at 10221.51,7162.44 h60
  text "Copper" at 11151.25,7162.44 h60
  text "1.40mil" at 12011.02,7162.44 h60
  text "6" at 9811.59,7042.44 h60
  text "Bottom Solder" at 10221.51,7042.44 h60
  text "Solder Resist" at 11151.25,7042.44 h60
  text "0.40mil" at 12011.02,7042.44 h60
  text "3.5" at 12660.85,7042.44 h60
  text "7" at 9811.59,6922.44 h60
  text "Bottom Overlay" at 10221.51,6922.44 h60
  text ".Layer_Name" at 577,-858.49 h60
M13 Component Bodies Top:
  text ".Layer_Name" at 577,-858.49 h60
M14 Component Bodies Bottom:
  text ".Layer_Name" at 577,-858.49 h60
M15 Courtyards Top:
  text ".Layer_Name" at 577,-858.49 h60
M16 Courtyards Bottom:
  text ".Layer_Name" at 577,-858.49 h60
Drill Drawing:
  circle w10: c5363.72,2947.32 r27.63
  lines w10: 5336.09,2671.06 5363.72,2684.87 5391.34,2671.06 5377.53,2698.68 5391.34,2726.31 5363.72,2712.5 5336.09,2726.31 5349.9,2698.68 5336.09,2671.06 ; 5336.09,2850.63 5391.34,2850.63 5363.72,2795.38 5336.09,2850.63 ; 5336.09,3044.02 5391.34,3044.02 5391.34,3099.27 5336.09,3099.27 5336.09,3044.02 ; 5336.09,3182.15 5349.9,3182.15 5349.9,3168.34 5377.53,3168.34 5377.53,3182.15 5391.34,3182.15 5391.34,3209.78 5377.53,3209.78 5377.53,3223.59 5349.9,3223.59 5349.9,3209.78 5336.09,3209.78 5336.09,3182.15 ; 5336.09,3306.47 5349.9,3306.47 5363.72,3292.66 5377.53,3306.47 5391.34,3306.47 5377.53,3320.28 5391.34,3334.1 5377.53,3334.1 5363.72,3347.91 5349.9,3334.1 5336.09,3334.1 5349.9,3320.28 5336.09,3306.47
  lines w12: 5286,2633.76 8517.49,2633.76 ; 5286,3379.68 8517.49,3379.68 ; 5623.86,2509.44 5623.86,3504 ; 5955.86,2509.44 5955.86,3504 ; 6592.43,2509.44 6592.43,3504 ; 6851.57,2509.44 6851.57,3504 ; 7226.72,2509.44 7226.72,3504 ; 7951.05,2509.44 7951.05,3504 ; 5286,2509.44 8517.49,2509.44 8517.49,3504 5286,3504 5286,2509.44
  text "Symbol" at 5360.59,3416.98 h72
  text "Quantity" at 5661.16,3416.98 h72
  text "Finished Hole Size" at 5993.16,3416.98 h72
  text "Plated" at 6629.72,3416.98 h72
  text "Hole Type" at 6888.86,3416.98 h72
  text "Drill Layer Pair" at 7264.02,3416.98 h72
  text "Hole Tolerance" at 7988.35,3416.98 h72
  text "1" at 5661.16,3292.66 h60
  text "12.00mil (0.305mm)" at 5993.16,3292.66 h60
  text "PTH" at 6629.72,3292.66 h60
  text "Round" at 6888.86,3292.66 h60
  text "Top Layer - Bottom Layer" at 7264.02,3292.66 h60
  text "2" at 5661.16,3168.34 h60
  text "15.00mil (0.381mm)" at 5993.16,3168.34 h60
  text "PTH" at 6629.72,3168.34 h60
  text "Round" at 6888.86,3168.34 h60
  text "Top Layer - Bottom Layer" at 7264.02,3168.34 h60
  text "2" at 5661.16,3044.02 h60
  text "31.00mil (0.787mm)" at 5993.16,3044.02 h60
  text "PTH" at 6629.72,3044.02 h60
  text "Round" at 6888.86,3044.02 h60
  text "Top Layer - Bottom Layer" at 7264.02,3044.02 h60
  text "2" at 5661.16,2919.7 h60
  text "33.47mil (0.850mm)" at 5993.16,2919.7 h60
  text "PTH" at 6629.72,2919.7 h60
  text "Round" at 6888.86,2919.7 h60
  text "Top Layer - Bottom Layer" at 7264.02,2919.7 h60
  text "4" at 5661.16,2795.38 h60
  text "40.00mil (1.016mm)" at 5993.16,2795.38 h60
  text "PTH" at 6629.72,2795.38 h60
  text "Round" at 6888.86,2795.38 h60
  text "Top Layer - Bottom Layer" at 7264.02,2795.38 h60
  text "6" at 5661.16,2671.06 h60
  text "42.91mil (1.090mm)" at 5993.16,2671.06 h60
  text "PTH" at 6629.72,2671.06 h60
  text "Round" at 6888.86,2671.06 h60
  text "Top Layer - Bottom Layer" at 7264.02,2671.06 h60
  text "17 Total" at 5661.16,2546.74 h60
  text ".Layer_Name" at 577,-858.49 h60
M17 Embedded Cavity:
  text ".Layer_Name" at 577,-858.49 h60
M18 Embedded Assembly:
  text ".Layer_Name" at 577,-858.49 h60
M19 Embedded Keepout:
  text ".Layer_Name" at 577,-858.49 h60

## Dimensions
0,-400 to 1000,-400 on M2 Board Dimensions
0,0 to 984.25,0 on M2 Board Dimensions
0,0 to 0,984.25 on M2 Board Dimensions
